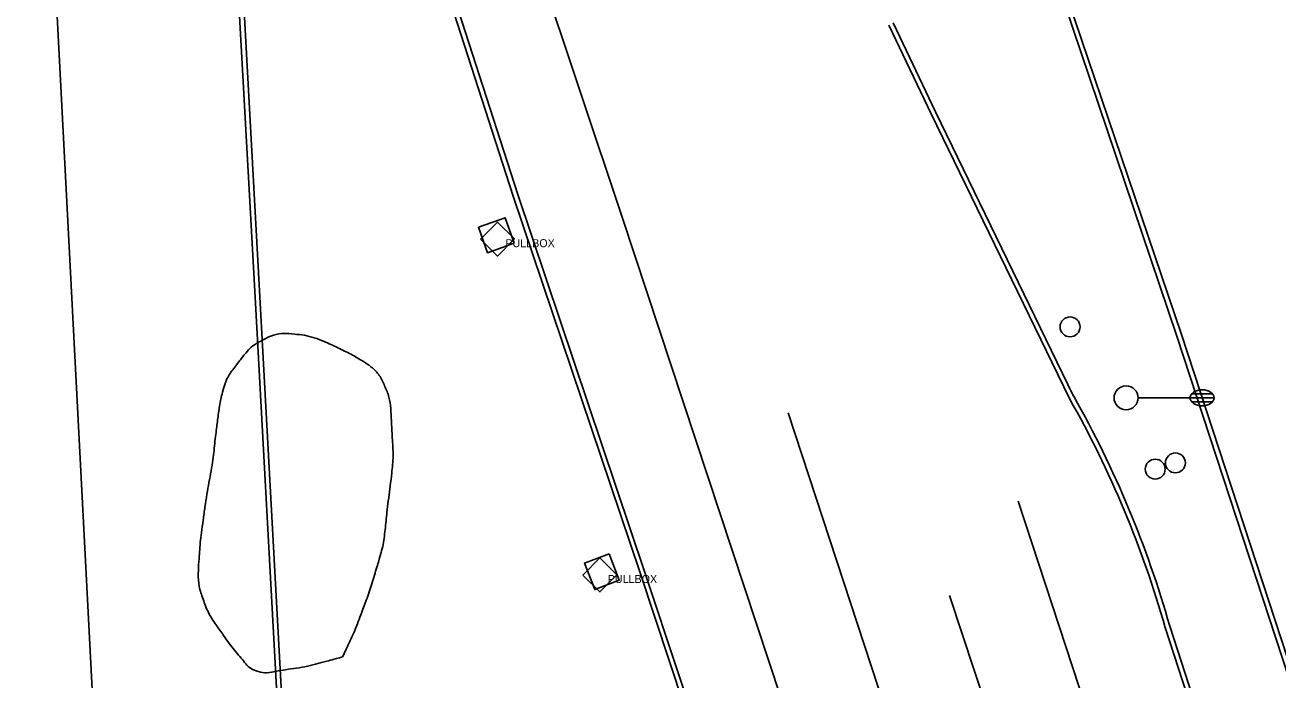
# Model space of a CAD drawing. Extents: x 2145380 to 2156929, y 139568 to 149130.
# Drawn here: x 2147135.8 to 2147292.3, y 143272 to 143353.8 of the extents above; entities that cross this region are included whole.
import ezdxf

# ---------------------------------------------------------------- set-up
doc = ezdxf.new("R2010")
doc.units = 0
for name, color, linetype in [('Default', 7, 'Continuous'), ('TOPO_Building', 7, 'Continuous'), ('TOPO_Concrete', 7, 'Continuous'), ('TOPO_Curb Back', 7, 'Continuous'), ('TOPO_Light Pole', 7, 'Continuous'), ('TOPO_Misc', 7, 'Continuous'), ('TOPO_Misc Line', 7, 'Continuous'), ('TOPO_Power Pullbox', 7, 'Continuous'), ('TOPO_Tree Line', 7, 'Continuous')]:
    doc.layers.add(name, color=color, linetype=linetype)

# ---------------------------------------------------------------- blocks, each defined once
blk = doc.blocks.new('LP')
at = {"layer": 'TOPO_Light Pole'}
blk.add_line((3.81, 0), (20.32, 0), dxfattribs=at)
for points in [[(20.32, 0), (27.94, 0)], [(20.32, 0), (23.5, 0)], [(20.83, 1.27), (27.43, 1.27)], [(20.83, 1.27), (23.5, 1.27)], [(23.71, 1.27), (27.43, 1.27)], [(23.71, 0), (27.94, 0)], [(20.83, -1.27), (27.43, -1.27)], [(20.83, -1.27), (23.5, -1.27)], [(23.71, -1.27), (27.43, -1.27)]]:
    blk.add_lwpolyline(points, dxfattribs=at)
blk.add_circle((0, 0), 3.81, dxfattribs=at)
blk.add_ellipse((24.13, 0), major_axis=(3.81, 0), ratio=0.666667, dxfattribs=at)
blk = doc.blocks.new('POST')
at = {"layer": 'TOPO_Misc'}
for start, end in [(90, 180), (180, 270), (360, 90), (270, 0)]:
    blk.add_arc((-0.01, 0.03), 3.16, start, end, dxfattribs=at)
blk = doc.blocks.new('pulbox')
at = {"layer": 'Default'}
blk.add_lwpolyline([(-5.38, -0.01), (-0.02, 5.42), (5.4, 0.06), (0.05, -5.36), (-5.38, -0.01)], dxfattribs=at)
blk.add_text('PULLBOX', height=2.54, dxfattribs=at).set_placement((2.54, -2.54))

msp = doc.modelspace()

# ---------------------------------------------------------------- linework, layer by layer
at = {"layer": 'TOPO_Building'}
msp.add_line((2147146.01, 143234.56), (2147137.32, 143402.27), dxfattribs=at)
at = {"layer": 'TOPO_Concrete'}
for points in [[(2147196.87, 143326.55), (2147193.55, 143325.36), (2147192.41, 143328.54), (2147195.73, 143329.72), (2147196.87, 143326.55)], [(2147208.74, 143287.76), (2147205.67, 143286.58), (2147206.93, 143283.28), (2147210, 143284.46), (2147208.74, 143287.76)]]:
    msp.add_lwpolyline(points, dxfattribs=at)
at = {"layer": 'TOPO_Curb Back'}
for p, q in [((2147265.53, 143356.75), (2147279.68, 143314.95)), ((2147266.1, 143356.94), (2147280.25, 143315.14)), ((2147248.96, 143342.71), (2147243.69, 143353.8)), ((2147249.5, 143342.97), (2147244.21, 143354.09)), ((2147266.24, 143307.14), (2147248.96, 143342.71)), ((2147266.77, 143307.42), (2147249.5, 143342.97)), ((2147279.68, 143314.95), (2147293.72, 143272.12)), ((2147280.25, 143315.14), (2147294.29, 143272.31)), ((2147294.19, 143229.56), (2147278.21, 143278.52)), ((2147294.76, 143229.75), (2147278.78, 143278.69))]:
    msp.add_line(p, q, dxfattribs=at)
for points in [[(2147103.78, 143616.14), (2147114.24, 143585.18), (2147126.8, 143547.4), (2147141.7, 143499.15), (2147161.24, 143440.63), (2147180.64, 143382.35), (2147196.74, 143332.44), (2147212.6, 143285.35), (2147225.45, 143246.61), (2147229.49, 143234.16)], [(2147104.33, 143616.36), (2147114.81, 143585.37), (2147127.37, 143547.58), (2147142.27, 143499.34), (2147161.81, 143440.82), (2147181.21, 143382.54), (2147197.31, 143332.63), (2147213.16, 143285.54), (2147226.02, 143246.79), (2147230.07, 143234.33)], [(2147167.49, 143264.93), (2147164.49, 143319.81), (2147161.9, 143366.93), (2147159.96, 143402.77), (2147143.75, 143458.08), (2147136.94, 143479.1)], [(2147168.09, 143264.97), (2147165.09, 143319.84), (2147162.5, 143366.96), (2147160.55, 143402.87), (2147144.33, 143458.26), (2147137.51, 143479.29)]]:
    msp.add_lwpolyline(points, dxfattribs=at)
for radius, start, end in [(130.51, 15.8335, 29.5377), (129.91, 15.8284, 29.5461)]:
    msp.add_arc((2147153.23, 143243.08), radius, start, end, dxfattribs=at)
at = {"layer": 'TOPO_Misc Line'}
for p, q in [((2147254.8, 143233.31), (2147231.08, 143305.34)), ((2147279.67, 143234), (2147259.84, 143294.34)), ((2147267.42, 143233.66), (2147251.24, 143282.55))]:
    msp.add_line(p, q, dxfattribs=at)
msp.add_lwpolyline([(2147242.33, 143232.97), (2147210.41, 143329.68), (2147184.07, 143408.45), (2147169.19, 143453.56), (2147149.47, 143513.78), (2147117.99, 143609.55)], dxfattribs=at)
at = {"layer": 'TOPO_Tree Line'}
msp.add_open_spline([(2147175.43, 143274.86), (2147175.81, 143275.69), (2147176.19, 143276.51), (2147176.57, 143277.34), (2147177.07, 143278.43), (2147177.49, 143279.55), (2147177.91, 143280.67), (2147178.68, 143282.72), (2147179.33, 143284.79), (2147179.95, 143286.9), (2147180.24, 143287.9), (2147180.52, 143288.91), (2147180.65, 143289.94), (2147180.78, 143291.03), (2147180.88, 143292.13), (2147181, 143293.22), (2147181.18, 143294.74), (2147181.39, 143296.25), (2147181.56, 143297.76), (2147181.81, 143299.98), (2147181.62, 143302.23), (2147181.52, 143304.46), (2147181.46, 143305.91), (2147181.29, 143307.33), (2147180.68, 143308.72), (2147180.08, 143310.09), (2147179.05, 143311.12), (2147177.82, 143311.89), (2147177.06, 143312.37), (2147176.29, 143312.78), (2147175.49, 143313.17), (2147174.6, 143313.6), (2147173.77, 143314), (2147172.82, 143314.38), (2147171.58, 143314.87), (2147170.34, 143315.11), (2147169.1, 143315.22), (2147167.79, 143315.33), (2147166.47, 143315.01), (2147165.16, 143314.3), (2147164.14, 143313.74), (2147163.49, 143313.06), (2147162.82, 143312.19), (2147161.82, 143310.9), (2147160.9, 143309.64), (2147160.48, 143308.11), (2147160.25, 143307.27), (2147160.07, 143306.42), (2147159.96, 143305.56), (2147159.84, 143304.69), (2147159.73, 143303.83), (2147159.62, 143302.96), (2147159.48, 143301.82), (2147159.37, 143300.67), (2147159.21, 143299.53), (2147159.02, 143298.09), (2147158.71, 143296.66), (2147158.48, 143295.22), (2147158.23, 143293.59), (2147158.01, 143291.96), (2147157.78, 143290.31), (2147157.63, 143289.15), (2147157.55, 143287.98), (2147157.47, 143286.82), (2147157.37, 143285.25), (2147157.43, 143283.68), (2147157.99, 143282.11), (2147158.61, 143280.34), (2147159.59, 143278.93), (2147160.63, 143277.45), (2147161.26, 143276.54), (2147161.9, 143275.72), (2147162.62, 143274.87), (2147163.19, 143274.19), (2147163.75, 143273.45), (2147164.61, 143273.15), (2147165.69, 143272.76), (2147166.84, 143273.03), (2147167.94, 143273.21), (2147169.31, 143273.43), (2147170.71, 143273.6), (2147172.06, 143273.96), (2147173.18, 143274.26), (2147174.31, 143274.56), (2147175.43, 143274.86)], degree=3, dxfattribs=at)

# ---------------------------------------------------------------- block references
at = {"layer": 'TOPO_Light Pole', "xscale": 0.39370000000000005, "yscale": 0.3937000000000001}
msp.add_blockref('LP', (2147273.32, 143307.23), dxfattribs=at)
at = {"layer": 'TOPO_Misc', "xscale": 0.39370000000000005, "yscale": 0.3937000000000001}
for p in [(2147266.33, 143316.08), (2147276.97, 143298.31), (2147279.49, 143299.09)]:
    msp.add_blockref('POST', p, dxfattribs=at)
at = {"layer": 'TOPO_Power Pullbox', "xscale": 0.39370000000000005, "yscale": 0.3937000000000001}
for p in [(2147194.77, 143327.05), (2147207.56, 143285.1)]:
    msp.add_blockref('pulbox', p, dxfattribs=at)

doc.saveas('drawing.dxf')
